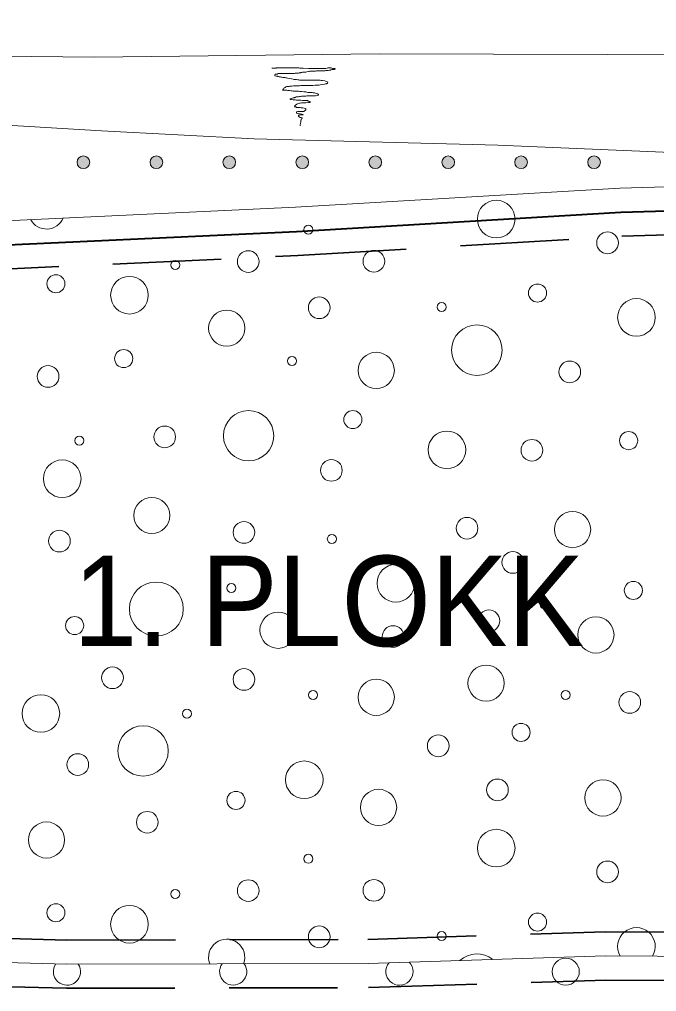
# Model space of a CAD drawing. Extents: x 640121 to 640955, y 6441885 to 6442246.
# Drawn here: x 640448.36 to 640469.5, y 6442180.31 to 6442212.56 of the extents above; entities that cross this region are included whole.
import ezdxf
from ezdxf.enums import TextEntityAlignment as Align

# ---------------------------------------------------------------- set-up
doc = ezdxf.new("R2010")
doc.units = 0
doc.header["$LTSCALE"] = 1.2
doc.linetypes.add('MEDIUM_DASHED', pattern=[4.5, 3, -1.5])
for name, color, linetype, lineweight in [('31', 7, 'Continuous', 13), ('35', 7, 'Continuous', 35), ('40', 7, 'Continuous', 13), ('41', 7, 'Continuous', 13), ('42', 7, 'Continuous', 13), ('45', 7, 'Continuous', 13)]:
    doc.layers.add(name, color=color, linetype=linetype, lineweight=lineweight)

msp = doc.modelspace()

# ---------------------------------------------------------------- hatches: boundary and pattern name
at = {"layer": '45'}
for points in [[(640450.697, 6442207.821, 1), (640450.277, 6442207.821, 1)], [(640453.117, 6442207.821, 1), (640452.697, 6442207.821, 1)], [(640455.537, 6442207.821, 1), (640455.117, 6442207.821, 1)], [(640457.957, 6442207.821, 1), (640457.537, 6442207.821, 1)], [(640460.377, 6442207.821, 1), (640459.957, 6442207.821, 1)], [(640462.797, 6442207.821, 1), (640462.377, 6442207.821, 1)], [(640465.217, 6442207.821, 1), (640464.797, 6442207.821, 1)], [(640467.637, 6442207.821, 1), (640467.217, 6442207.821, 1)]]:
    msp.add_hatch(color=256, dxfattribs=at).paths.add_polyline_path(points)

# ---------------------------------------------------------------- linework, layer by layer
at = {"layer": '31'}
for points in [[(640362.7, 6442207.53), (640371.1, 6442207.66), (640378.91, 6442207.96), (640387.66, 6442208.39), (640395.09, 6442208.91), (640403.04, 6442209.13), (640410.1, 6442209.62), (640417.94, 6442210.22), (640426.11, 6442210.87), (640434.35, 6442211.6), (640443.55, 6442211.39), (640450.84, 6442211.31), (640460.31, 6442211.42), (640471.64, 6442211.39), (640480.39, 6442211.46), (640490.9, 6442211.02), (640496.37, 6442211.02), (640502.28, 6442211.46), (640506.95, 6442212.04), (640510.5, 6442212.56)], [(640362.55, 6442203.68), (640369.1, 6442203.88), (640381.31, 6442204.1), (640393.24, 6442204.9), (640403.15, 6442205.61), (640412.11, 6442206.42), (640420.43, 6442207.78), (640428.21, 6442208.95), (640434.36, 6442209.59), (640443.5, 6442209.32), (640451.09, 6442208.86), (640456.15, 6442208.6), (640464.23, 6442208.39), (640474.43, 6442207.96), (640479.86, 6442207.51), (640485.77, 6442207.28), (640492.16, 6442206.96), (640495.99, 6442206.92), (640502.28, 6442207.34), (640510.5, 6442208.25)], [(640393.24, 6442204.9), (640408.33, 6442204.95), (640419.16, 6442205.43), (640427.3, 6442205.52), (640434.54, 6442205.7), (640446.03, 6442205.79), (640457.52, 6442206.33), (640468.28, 6442206.96), (640474.79, 6442207.15), (640481.17, 6442207.46)], [(640361.87, 6442180.35), (640370.38, 6442181.71), (640378.83, 6442182.99), (640382.86, 6442183.28), (640390.58, 6442183.39), (640398.35, 6442183.34), (640407.42, 6442182.84), (640417.38, 6442182.24), (640426.85, 6442181.64), (640434.32, 6442181.74), (640441.06, 6442181.46), (640449.93, 6442181.22), (640459.93, 6442181.24), (640467.81, 6442181.49), (640476.37, 6442181.44), (640484.64, 6442181.24), (640496.4, 6442181.04), (640502.87, 6442181.04), (640510.5, 6442181.13)]]:
    msp.add_lwpolyline(points, dxfattribs=at)
at = {"layer": '35', "lineweight": 40}
msp.add_lwpolyline([(640393.27, 6442204.1), (640408.35, 6442204.15), (640419.19, 6442204.63), (640427.32, 6442204.72), (640434.55, 6442204.9), (640446.05, 6442204.99), (640457.56, 6442205.53), (640468.31, 6442206.17), (640474.82, 6442206.35), (640481.18, 6442206.66)], dxfattribs=at)
at = {"layer": '35', "linetype": 'MEDIUM_DASHED'}
for points in [[(640393.27, 6442203.3), (640408.37, 6442203.35), (640419.21, 6442203.83), (640427.33, 6442203.92), (640434.57, 6442204.1), (640446.07, 6442204.19), (640457.6, 6442204.73), (640468.35, 6442205.37), (640474.85, 6442205.55), (640481.22, 6442205.86)], [(640379.57, 6442183.85), (640382.82, 6442184.08), (640390.58, 6442184.19), (640398.38, 6442184.14), (640407.47, 6442183.64), (640417.43, 6442183.04), (640426.87, 6442182.44), (640434.33, 6442182.54), (640441.09, 6442182.26), (640449.94, 6442182.02), (640459.92, 6442182.04), (640467.8, 6442182.29), (640476.38, 6442182.24), (640484.66, 6442182.04), (640494.87, 6442181.87)], [(640377.97, 6442182.13), (640382.89, 6442182.48), (640390.58, 6442182.59), (640398.33, 6442182.54), (640407.37, 6442182.04), (640417.33, 6442181.44), (640426.83, 6442180.84), (640434.31, 6442180.94), (640441.03, 6442180.66), (640449.92, 6442180.42), (640459.94, 6442180.44), (640467.82, 6442180.69), (640476.36, 6442180.64), (640484.62, 6442180.44), (640494.87, 6442180.27)]]:
    msp.add_lwpolyline(points, dxfattribs=at)
at = {"layer": '40'}
for points in [[(640456.74, 6442210.94), (640456.77, 6442210.94), (640456.82, 6442210.94), (640456.88, 6442210.94), (640456.89, 6442210.95), (640456.94, 6442210.95), (640457.02, 6442210.95), (640457.18, 6442210.95), (640457.27, 6442210.95), (640457.29, 6442210.95), (640457.31, 6442210.95), (640457.35, 6442210.95), (640457.39, 6442210.95), (640457.44, 6442210.95), (640457.48, 6442210.95), (640457.51, 6442210.95), (640457.56, 6442210.95), (640457.59, 6442210.95), (640457.63, 6442210.95), (640457.67, 6442210.94), (640457.69, 6442210.94), (640457.73, 6442210.94), (640457.78, 6442210.94), (640457.95, 6442210.93), (640458.1, 6442210.93), (640458.15, 6442210.93), (640458.18, 6442210.93), (640458.2, 6442210.93), (640458.22, 6442210.93), (640458.26, 6442210.93), (640458.31, 6442210.93), (640458.33, 6442210.93), (640458.35, 6442210.93), (640458.36, 6442210.93), (640458.38, 6442210.93), (640458.41, 6442210.93), (640458.43, 6442210.93), (640458.46, 6442210.93), (640458.5, 6442210.93), (640458.53, 6442210.93), (640458.57, 6442210.94), (640458.59, 6442210.95), (640458.62, 6442210.95), (640458.64, 6442210.95), (640458.67, 6442210.95), (640458.69, 6442210.95), (640458.71, 6442210.95), (640458.73, 6442210.94), (640458.75, 6442210.93), (640458.77, 6442210.93)], [(640457.51, 6442210.78), (640457.49, 6442210.77), (640457.46, 6442210.77), (640457.44, 6442210.77), (640457.42, 6442210.77), (640457.41, 6442210.77), (640457.38, 6442210.77), (640457.36, 6442210.77), (640457.33, 6442210.77), (640457.3, 6442210.77), (640457.28, 6442210.77), (640457.25, 6442210.77), (640457.23, 6442210.77), (640457.21, 6442210.77), (640457.2, 6442210.77), (640457.17, 6442210.77), (640457.15, 6442210.77), (640457.11, 6442210.77), (640457.09, 6442210.77), (640457.08, 6442210.77), (640457.05, 6442210.77), (640457.03, 6442210.77), (640457, 6442210.77), (640456.99, 6442210.77), (640456.96, 6442210.77), (640456.94, 6442210.77), (640456.92, 6442210.75), (640456.9, 6442210.75), (640456.88, 6442210.75), (640456.87, 6442210.74), (640456.85, 6442210.74), (640456.84, 6442210.72), (640456.84, 6442210.71), (640456.84, 6442210.69), (640456.89, 6442210.68), (640456.92, 6442210.68), (640456.94, 6442210.67), (640456.96, 6442210.67), (640456.98, 6442210.66), (640456.99, 6442210.66), (640457.02, 6442210.66), (640457.05, 6442210.65), (640457.06, 6442210.65), (640457.1, 6442210.63), (640457.14, 6442210.63), (640457.17, 6442210.63), (640457.2, 6442210.62), (640457.22, 6442210.62), (640457.26, 6442210.61), (640457.32, 6442210.6)], [(640458.77, 6442210.93), (640458.79, 6442210.93), (640458.81, 6442210.93), (640458.83, 6442210.93), (640458.85, 6442210.92), (640458.83, 6442210.91), (640458.84, 6442210.92), (640458.82, 6442210.91), (640458.8, 6442210.9), (640458.77, 6442210.9), (640458.75, 6442210.9), (640458.73, 6442210.9), (640458.71, 6442210.89), (640458.69, 6442210.89), (640458.68, 6442210.88), (640458.65, 6442210.88), (640458.61, 6442210.87), (640458.59, 6442210.87), (640458.53, 6442210.87), (640458.51, 6442210.86), (640458.49, 6442210.86), (640458.47, 6442210.86), (640458.44, 6442210.86), (640458.43, 6442210.86), (640458.4, 6442210.85), (640458.38, 6442210.85), (640458.32, 6442210.85), (640458.29, 6442210.85), (640458.26, 6442210.85), (640458.22, 6442210.85), (640458.19, 6442210.84), (640458.16, 6442210.84), (640458.13, 6442210.84), (640458.1, 6442210.84), (640458.02, 6442210.84), (640458, 6442210.84), (640457.98, 6442210.83), (640457.95, 6442210.83), (640457.9, 6442210.82), (640457.86, 6442210.81), (640457.83, 6442210.81), (640457.78, 6442210.81), (640457.75, 6442210.81), (640457.73, 6442210.8), (640457.7, 6442210.8), (640457.69, 6442210.79), (640457.67, 6442210.79), (640457.64, 6442210.79), (640457.62, 6442210.78), (640457.6, 6442210.78), (640457.53, 6442210.78), (640457.51, 6442210.78)], [(640457.92, 6442210.37), (640457.88, 6442210.37), (640457.84, 6442210.37), (640457.8, 6442210.37), (640457.77, 6442210.37), (640457.74, 6442210.37), (640457.7, 6442210.37), (640457.66, 6442210.36), (640457.57, 6442210.36), (640457.53, 6442210.36), (640457.5, 6442210.36), (640457.46, 6442210.36), (640457.4, 6442210.35), (640457.33, 6442210.35), (640457.31, 6442210.34), (640457.28, 6442210.34), (640457.27, 6442210.33), (640457.25, 6442210.33), (640457.23, 6442210.33), (640457.21, 6442210.32), (640457.2, 6442210.32), (640457.18, 6442210.3), (640457.15, 6442210.29), (640457.14, 6442210.27), (640457.13, 6442210.26), (640457.11, 6442210.26), (640457.11, 6442210.24), (640457.09, 6442210.23), (640457.09, 6442210.22), (640457.1, 6442210.21), (640457.12, 6442210.21), (640457.15, 6442210.21), (640457.17, 6442210.21), (640457.23, 6442210.21), (640457.27, 6442210.2), (640457.32, 6442210.2), (640457.38, 6442210.19), (640457.41, 6442210.19), (640457.44, 6442210.18), (640457.47, 6442210.18), (640457.55, 6442210.18), (640457.62, 6442210.18), (640457.67, 6442210.17), (640457.72, 6442210.17), (640457.8, 6442210.16), (640457.87, 6442210.16), (640457.93, 6442210.14), (640457.97, 6442210.14), (640458.02, 6442210.14), (640458.06, 6442210.14)], [(640457.32, 6442210.6), (640457.39, 6442210.59), (640457.44, 6442210.58), (640457.47, 6442210.57), (640457.51, 6442210.57), (640457.56, 6442210.57), (640457.6, 6442210.56), (640457.63, 6442210.56), (640457.65, 6442210.55), (640457.69, 6442210.55), (640457.72, 6442210.55), (640457.77, 6442210.54), (640457.81, 6442210.54), (640457.84, 6442210.54), (640457.89, 6442210.54), (640457.93, 6442210.54), (640457.96, 6442210.54), (640457.98, 6442210.54), (640458.02, 6442210.54), (640458.05, 6442210.54), (640458.1, 6442210.54), (640458.14, 6442210.54), (640458.19, 6442210.54), (640458.22, 6442210.54), (640458.26, 6442210.54), (640458.28, 6442210.54), (640458.31, 6442210.54), (640458.34, 6442210.54), (640458.37, 6442210.53), (640458.4, 6442210.53), (640458.42, 6442210.53), (640458.49, 6442210.52), (640458.52, 6442210.51), (640458.55, 6442210.5), (640458.57, 6442210.49), (640458.59, 6442210.48), (640458.59, 6442210.47), (640458.58, 6442210.45), (640458.57, 6442210.44), (640458.56, 6442210.44), (640458.55, 6442210.42), (640458.52, 6442210.42), (640458.48, 6442210.41), (640458.41, 6442210.4), (640458.34, 6442210.39), (640458.31, 6442210.38), (640458.26, 6442210.38), (640458.22, 6442210.38), (640458.17, 6442210.38), (640458.1, 6442210.37), (640458.01, 6442210.37), (640457.92, 6442210.37)], [(640458.06, 6442210.14), (640458.08, 6442210.14), (640458.11, 6442210.13), (640458.15, 6442210.12), (640458.19, 6442210.11), (640458.21, 6442210.1), (640458.23, 6442210.09), (640458.26, 6442210.09), (640458.28, 6442210.08), (640458.28, 6442210.06), (640458.27, 6442210.05), (640458.26, 6442210.05), (640458.24, 6442210.04), (640458.18, 6442210.03), (640458.15, 6442210.03), (640458.13, 6442210.03), (640458.1, 6442210.03), (640458.05, 6442210.03), (640458.01, 6442210.03), (640457.99, 6442210.03), (640457.96, 6442210.03), (640457.9, 6442210.03), (640457.86, 6442210.02), (640457.84, 6442210.02), (640457.81, 6442210.02), (640457.8, 6442210.01), (640457.77, 6442210.01), (640457.72, 6442210.01), (640457.69, 6442210), (640457.65, 6442210), (640457.62, 6442209.99), (640457.6, 6442209.99), (640457.57, 6442209.99), (640457.56, 6442209.99), (640457.53, 6442209.99), (640457.52, 6442209.97), (640457.49, 6442209.97), (640457.48, 6442209.96), (640457.46, 6442209.96), (640457.44, 6442209.96), (640457.41, 6442209.95), (640457.38, 6442209.94), (640457.35, 6442209.93), (640457.34, 6442209.92), (640457.34, 6442209.9), (640457.36, 6442209.9), (640457.39, 6442209.9), (640457.44, 6442209.89), (640457.48, 6442209.89), (640457.51, 6442209.89), (640457.56, 6442209.88), (640457.59, 6442209.88)], [(640457.59, 6442209.88), (640457.6, 6442209.88), (640457.62, 6442209.88), (640457.65, 6442209.88), (640457.68, 6442209.88), (640457.7, 6442209.88), (640457.75, 6442209.87), (640457.8, 6442209.87), (640457.81, 6442209.87), (640457.84, 6442209.87), (640457.86, 6442209.87), (640457.89, 6442209.87), (640457.92, 6442209.87), (640457.94, 6442209.85), (640457.96, 6442209.85), (640457.99, 6442209.84), (640458.01, 6442209.84), (640458.01, 6442209.81), (640457.95, 6442209.8), (640457.87, 6442209.79), (640457.84, 6442209.79), (640457.78, 6442209.79), (640457.75, 6442209.79), (640457.72, 6442209.79), (640457.68, 6442209.78), (640457.65, 6442209.78), (640457.61, 6442209.77), (640457.57, 6442209.75), (640457.56, 6442209.74), (640457.53, 6442209.73), (640457.52, 6442209.72), (640457.51, 6442209.7), (640457.5, 6442209.69), (640457.49, 6442209.67), (640457.5, 6442209.66), (640457.53, 6442209.66), (640457.56, 6442209.64), (640457.63, 6442209.64), (640457.68, 6442209.64), (640457.71, 6442209.63), (640457.74, 6442209.63), (640457.77, 6442209.63), (640457.81, 6442209.62), (640457.86, 6442209.6), (640457.86, 6442209.58), (640457.86, 6442209.56), (640457.85, 6442209.55), (640457.81, 6442209.52), (640457.8, 6442209.51), (640457.77, 6442209.51), (640457.72, 6442209.51), (640457.68, 6442209.51), (640457.65, 6442209.51), (640457.6, 6442209.51), (640457.56, 6442209.5), (640457.56, 6442209.48), (640457.55, 6442209.47), (640457.56, 6442209.46), (640457.57, 6442209.45), (640457.63, 6442209.43), (640457.68, 6442209.43), (640457.7, 6442209.42), (640457.73, 6442209.42), (640457.76, 6442209.41), (640457.78, 6442209.4), (640457.77, 6442209.39), (640457.74, 6442209.39), (640457.7, 6442209.39), (640457.65, 6442209.38), (640457.63, 6442209.38), (640457.62, 6442209.37), (640457.62, 6442209.35), (640457.63, 6442209.34), (640457.64, 6442209.33), (640457.66, 6442209.32), (640457.68, 6442209.31), (640457.71, 6442209.31), (640457.74, 6442209.3), (640457.74, 6442209.28), (640457.73, 6442209.27), (640457.72, 6442209.25), (640457.71, 6442209.23), (640457.7, 6442209.22), (640457.7, 6442209.19), (640457.7, 6442209.17), (640457.7, 6442209.15), (640457.69, 6442209.13), (640457.69, 6442209.11), (640457.69, 6442209.1), (640457.68, 6442209.07), (640457.68, 6442209.06), (640457.68, 6442209.03), (640457.68, 6442209.03), (640457.68, 6442209.04)]]:
    msp.add_lwpolyline(points, dxfattribs=at)
at = {"layer": '41'}
for centre, radius in [((640464.181, 6442205.937), 0.624), ((640457.951, 6442205.583), 0.15), ((640467.873, 6442205.149), 0.36), ((640455.955, 6442204.527), 0.36), ((640460.122, 6442204.537), 0.36), ((640453.532, 6442204.416), 0.15), ((640449.575, 6442203.792), 0.3), ((640452.014, 6442203.412), 0.624), ((640465.55, 6442203.483), 0.3), ((640458.308, 6442202.995), 0.36), ((640468.832, 6442202.676), 0.624), ((640455.239, 6442202.319), 0.6), ((640462.37, 6442203.018), 0.15), ((640463.54, 6442201.59), 0.838), ((640451.822, 6442201.308), 0.3), ((640457.408, 6442201.23), 0.15), ((640460.201, 6442200.918), 0.6), ((640449.314, 6442200.716), 0.36), ((640466.619, 6442200.868), 0.36), ((640455.966, 6442198.749), 0.834), ((640459.424, 6442199.286), 0.3), ((640453.183, 6442198.709), 0.36), ((640450.352, 6442198.587), 0.15), ((640462.546, 6442198.281), 0.624), ((640468.574, 6442198.587), 0.3), ((640465.365, 6442198.266), 0.36), ((640449.783, 6442197.323), 0.624), ((640458.711, 6442197.601), 0.36), ((640452.755, 6442196.103), 0.6), ((640466.714, 6442195.635), 0.6), ((640455.813, 6442195.542), 0.36), ((640463.212, 6442195.68), 0.36), ((640449.689, 6442195.256), 0.36), ((640458.728, 6442195.326), 0.15), ((640464.731, 6442194.548), 0.36), ((640460.85, 6442193.855), 0.624), ((640452.906, 6442193.002), 0.893), ((640468.73, 6442193.616), 0.3), ((640455.392, 6442193.694), 0.15), ((640465.784, 6442193.151), 0.15), ((640463.939, 6442192.61), 0.36), ((640450.196, 6442192.452), 0.3), ((640456.943, 6442192.296), 0.6), ((640467.488, 6442192.14), 0.6), ((640460.758, 6442192.085), 0.36), ((640451.451, 6442190.72), 0.36), ((640455.813, 6442190.664), 0.36), ((640463.843, 6442190.54), 0.6), ((640460.201, 6442190.072), 0.6), ((640449.076, 6442189.534), 0.624), ((640458.107, 6442190.15), 0.15), ((640466.48, 6442190.15), 0.15), ((640468.609, 6442189.903), 0.36), ((640453.919, 6442189.529), 0.15), ((640452.467, 6442188.292), 0.835), ((640465.007, 6442188.908), 0.3), ((640462.258, 6442188.462), 0.36), ((640450.299, 6442187.839), 0.36), ((640457.813, 6442187.336), 0.624), ((640464.222, 6442187.001), 0.36), ((640467.722, 6442186.733), 0.6), ((640455.548, 6442186.652), 0.3), ((640460.279, 6442186.421), 0.6), ((640452.606, 6442185.925), 0.36), ((640449.263, 6442185.338), 0.6), ((640464.181, 6442185.068), 0.624), ((640457.951, 6442184.714), 0.15), ((640467.873, 6442184.28), 0.36), ((640455.955, 6442183.658), 0.36), ((640460.122, 6442183.668), 0.36), ((640453.532, 6442183.547), 0.15), ((640449.575, 6442182.923), 0.3), ((640452.014, 6442182.543), 0.624), ((640465.55, 6442182.614), 0.3), ((640458.308, 6442182.126), 0.36), ((640462.37, 6442182.149), 0.15)]:
    msp.add_circle(centre, radius, dxfattribs=at)
for centre, radius, start, end in [((640449.263, 6442206.207), 0.6, 208.9506, 336.4591), ((640468.832, 6442181.807), 0.624, 328.5057, 210.8627), ((640455.239, 6442181.45), 0.6, 338.8446, 201.4253), ((640463.54, 6442180.721), 0.838, 51.0781, 132.5043)]:
    msp.add_arc(centre, radius, start, end, dxfattribs=at)
at = {"layer": '42'}
msp.add_circle((640466.486, 6442180.971), 0.45, dxfattribs=at)
for centre, start, end in [((640449.94, 6442180.971), 144.84, 33.8017), ((640455.455, 6442180.971), 144.4571, 35.8128), ((640460.97, 6442180.971), 139.0516, 44.5308)]:
    msp.add_arc(centre, 0.45, start, end, dxfattribs=at)
at = {"layer": '45'}
for centre in [(640450.487, 6442207.821), (640452.907, 6442207.821), (640455.327, 6442207.821), (640457.747, 6442207.821), (640460.167, 6442207.821), (640462.587, 6442207.821), (640465.007, 6442207.821), (640467.427, 6442207.821)]:
    msp.add_circle(centre, 0.21, dxfattribs=at)

# ---------------------------------------------------------------- texts
at = {"layer": '35', "width": 0.95}
msp.add_text('1. PLOKK', height=3, dxfattribs=at).set_placement((640458.625, 6442191.77), align=Align.CENTER)

doc.saveas('drawing.dxf')
